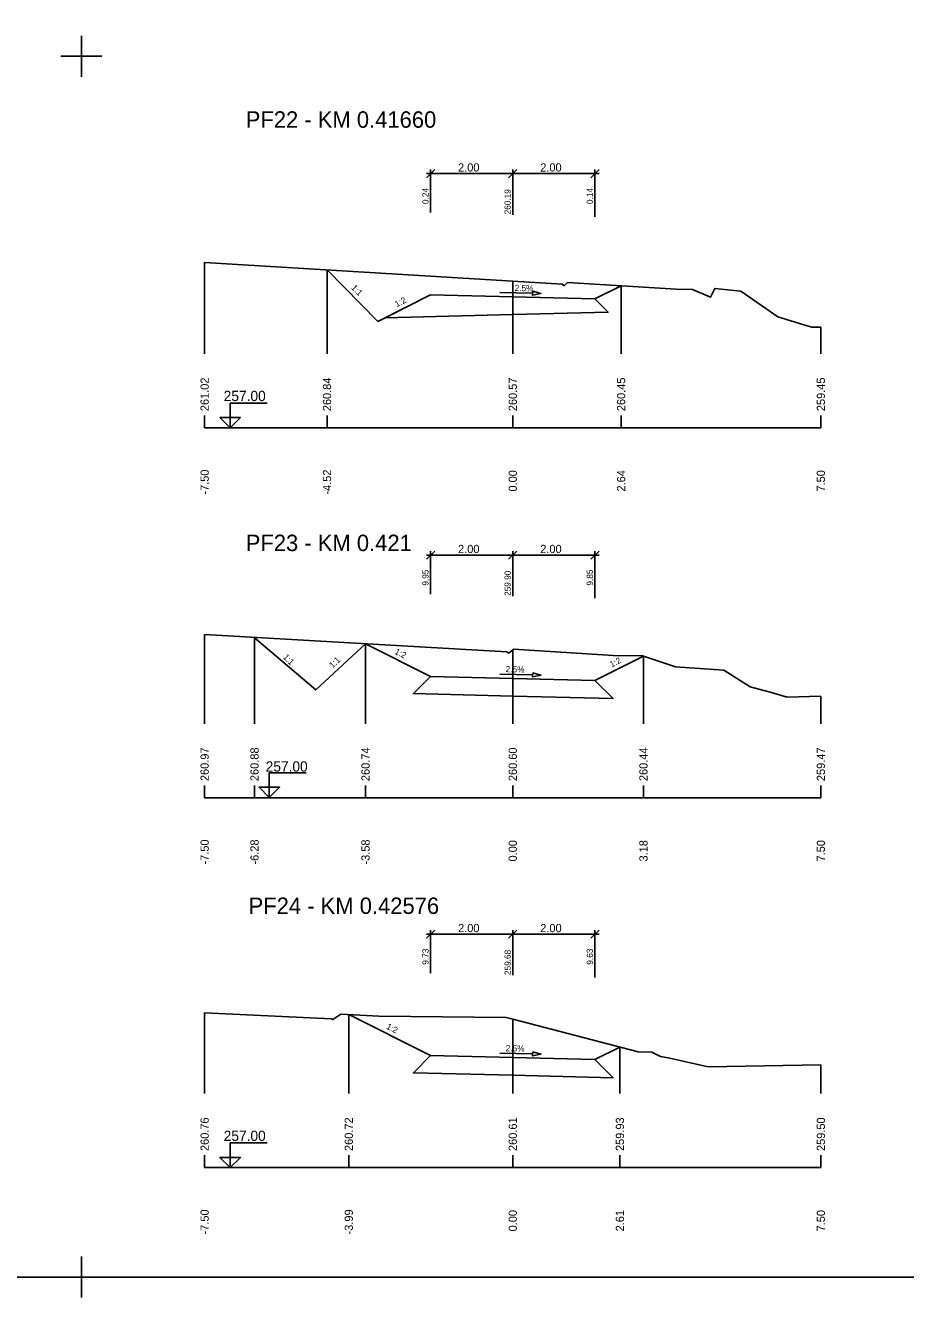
# Model space of a CAD drawing. Extents: x -5 to 1895, y -2 to 602.
# Drawn here: x 1456.4 to 1670.6, y -1.6 to 307.9 of the extents above; entities that cross this region are included whole.
import ezdxf

# ---------------------------------------------------------------- set-up
doc = ezdxf.new("R2010")
doc.units = 0
for name, color, linetype in [('KOTA', 7, 'Continuous'), ('KOTA_DELKY', 7, 'Continuous'), ('KOTA_DELKY_CONT', 7, 'Continuous'), ('NS_TELESO_VOZOVKY', 7, 'Continuous'), ('NS_V_PF', 7, 'Continuous'), ('REZY_PF_PUVODNI', 7, 'Continuous'), ('SESTAVY_REZU_PF', 7, 'Continuous'), ('SKLON', 7, 'Continuous'), ('SVK', 7, 'Continuous')]:
    doc.layers.add(name, color=color, linetype=linetype)

msp = doc.modelspace()

# ---------------------------------------------------------------- linework, layer by layer
for p, q in [((1470, 305.39), (1470, 295.39)), ((1470, 305.39), (1470, 295.39)), ((1470, 305.39), (1470, 295.39)), ((1470, 305.39), (1470, 295.39)), ((1470, 305.39), (1470, 295.39)), ((1470, 305.39), (1470, 295.39)), ((1470, 305.39), (1470, 295.39)), ((1470, 305.39), (1470, 295.39)), ((1470, 305.39), (1470, 295.39)), ((1470, 305.39), (1470, 295.39)), ((1470, 305.39), (1470, 295.39)), ((1470, 305.39), (1470, 295.39)), ((1470, 305.39), (1470, 295.39)), ((1470, 305.39), (1470, 295.39)), ((1470, 305.39), (1470, 295.39)), ((1470, 305.39), (1470, 295.39)), ((1470, 305.39), (1470, 295.39)), ((1470, 305.39), (1470, 295.39)), ((1470, 305.39), (1470, 295.39)), ((1470, 305.39), (1470, 295.39)), ((1470, 305.39), (1470, 295.39)), ((1470, 305.39), (1470, 295.39)), ((1470, 305.39), (1470, 295.39)), ((1470, 305.39), (1470, 295.39)), ((1470, 305.39), (1470, 295.39)), ((1470, 305.39), (1470, 295.39)), ((1470, 305.39), (1470, 295.39)), ((1470, 305.39), (1470, 295.39)), ((1470, 305.39), (1470, 295.39)), ((1470, 305.39), (1470, 295.39)), ((1475, 300.39), (1465, 300.39)), ((1475, 300.39), (1465, 300.39)), ((1475, 300.39), (1465, 300.39)), ((1475, 300.39), (1465, 300.39)), ((1475, 300.39), (1465, 300.39)), ((1475, 300.39), (1465, 300.39)), ((1475, 300.39), (1465, 300.39)), ((1475, 300.39), (1465, 300.39)), ((1475, 300.39), (1465, 300.39)), ((1475, 300.39), (1465, 300.39)), ((1475, 300.39), (1465, 300.39)), ((1475, 300.39), (1465, 300.39)), ((1475, 300.39), (1465, 300.39)), ((1475, 300.39), (1465, 300.39)), ((1475, 300.39), (1465, 300.39)), ((1475, 300.39), (1465, 300.39)), ((1475, 300.39), (1465, 300.39)), ((1475, 300.39), (1465, 300.39)), ((1475, 300.39), (1465, 300.39)), ((1475, 300.39), (1465, 300.39)), ((1475, 300.39), (1465, 300.39)), ((1475, 300.39), (1465, 300.39)), ((1475, 300.39), (1465, 300.39)), ((1475, 300.39), (1465, 300.39)), ((1475, 300.39), (1465, 300.39)), ((1475, 300.39), (1465, 300.39)), ((1475, 300.39), (1465, 300.39)), ((1475, 300.39), (1465, 300.39)), ((1475, 300.39), (1465, 300.39)), ((1475, 300.39), (1465, 300.39)), ((1470, 8.39), (1470, -1.61)), ((1470, 8.39), (1470, -1.61)), ((1470, 8.39), (1470, -1.61)), ((1470, 8.39), (1470, -1.61)), ((1470, 8.39), (1470, -1.61)), ((1470, 8.39), (1470, -1.61)), ((1470, 8.39), (1470, -1.61)), ((1470, 8.39), (1470, -1.61)), ((1470, 8.39), (1470, -1.61)), ((1470, 8.39), (1470, -1.61)), ((1470, 8.39), (1470, -1.61)), ((1470, 8.39), (1470, -1.61)), ((1475, 3.39), (1465, 3.39)), ((1475, 3.39), (1465, 3.39)), ((1475, 3.39), (1465, 3.39)), ((1475, 3.39), (1465, 3.39)), ((1475, 3.39), (1465, 3.39)), ((1475, 3.39), (1465, 3.39)), ((1475, 3.39), (1465, 3.39)), ((1475, 3.39), (1465, 3.39)), ((1475, 3.39), (1465, 3.39)), ((1475, 3.39), (1465, 3.39)), ((1475, 3.39), (1465, 3.39)), ((1475, 3.39), (1465, 3.39))]:
    msp.add_line(p, q)
msp.add_lwpolyline([(0, 597.39), (1890, 597.39), (1890, 3.39), (0, 3.39)], close=True)
at = {"layer": 'KOTA'}
for points in [[(1506.22, 212.5), (1503.72, 212.5), (1506.22, 210), (1506.22, 216), (1515.22, 216)], [(1506.22, 210), (1508.72, 212.5), (1506.22, 212.5)], [(1515.74, 122.55), (1513.24, 122.55), (1515.74, 120.05), (1515.74, 126.05), (1524.74, 126.05)], [(1515.74, 120.05), (1518.24, 122.55), (1515.74, 122.55)], [(1506.22, 32.5), (1503.72, 32.5), (1506.22, 30), (1506.22, 36), (1515.22, 36)], [(1506.22, 30), (1508.72, 32.5), (1506.22, 32.5)]]:
    msp.add_lwpolyline(points, dxfattribs=at)
at = {"layer": 'KOTA_DELKY'}
for points in [[(1554, 270.85), (1556, 272.85)], [(1555, 262.35), (1555, 272.85)], [(1574, 270.85), (1576, 272.85)], [(1574, 270.85), (1576, 272.85)], [(1575, 261.85), (1575, 272.85)], [(1575, 261.85), (1575, 272.85)], [(1594, 270.85), (1596, 272.85)], [(1595, 261.35), (1595, 272.85)], [(1554, 271.85), (1576, 271.85)], [(1574, 271.85), (1596, 271.85)], [(1554, 178.02), (1556, 180.02)], [(1555, 169.52), (1555, 180.02)], [(1574, 178.02), (1576, 180.02)], [(1574, 178.02), (1576, 180.02)], [(1575, 169.02), (1575, 180.02)], [(1575, 169.02), (1575, 180.02)], [(1594, 178.02), (1596, 180.02)], [(1595, 168.52), (1595, 180.02)], [(1554, 179.02), (1576, 179.02)], [(1574, 179.02), (1596, 179.02)], [(1554, 85.79), (1556, 87.79)], [(1554, 86.79), (1576, 86.79)], [(1555, 77.29), (1555, 87.79)], [(1574, 85.79), (1576, 87.79)], [(1574, 85.79), (1576, 87.79)], [(1574, 86.79), (1596, 86.79)], [(1575, 76.79), (1575, 87.79)], [(1575, 76.79), (1575, 87.79)], [(1594, 85.79), (1596, 87.79)], [(1595, 76.29), (1595, 87.79)]]:
    msp.add_lwpolyline(points, dxfattribs=at)
at = {"layer": 'NS_TELESO_VOZOVKY'}
for points in [[(1575, 241.85), (1595, 241.35), (1595, 241.35), (1598.22, 238.13), (1575, 237.55), (1543.97, 236.78), (1555, 242.35), (1555, 242.35), (1575, 241.85)], [(1575, 149.02), (1595, 148.52), (1595, 148.52), (1599.41, 144.11), (1575, 144.72), (1550.8, 145.32), (1555, 149.52), (1555, 149.52), (1575, 149.02)], [(1575, 56.79), (1595, 56.29), (1595, 56.29), (1599.41, 51.88), (1575, 52.49), (1550.8, 53.09), (1555, 57.29), (1555, 57.29), (1575, 56.79)]]:
    msp.add_lwpolyline(points, dxfattribs=at)
at = {"layer": 'NS_V_PF'}
for points in [[(1529.79, 248.41), (1542.19, 235.88), (1555, 242.35), (1555, 242.35), (1575, 241.85), (1595, 241.35), (1595, 241.35), (1601.38, 244.54)], [(1512.04, 158.99), (1527.04, 146.23), (1539.16, 157.44)], [(1539.16, 157.44), (1555, 149.52), (1555, 149.52), (1575, 149.02), (1595, 148.52), (1595, 148.52), (1606.81, 154.42)], [(1535.09, 67.24), (1555, 57.29), (1555, 57.29), (1575, 56.79), (1595, 56.29), (1595, 56.29), (1601.08, 59.33)]]:
    msp.add_lwpolyline(points, dxfattribs=at)
at = {"layer": 'REZY_PF_PUVODNI'}
for points in [[(1500, 250.19), (1575, 245.7), (1587.01, 244.98), (1587.54, 244.54), (1588.36, 245.37), (1614.74, 243.69), (1618.72, 243.63), (1623.15, 241.79), (1624.15, 243.92), (1630.5, 243.26), (1639.56, 236.96), (1645.84, 235.09), (1647.82, 234.45), (1650, 234.51)], [(1500, 159.68), (1573.59, 155.46), (1574.03, 155.13), (1575, 156), (1575.18, 156.16), (1600.74, 154.54), (1606.32, 154.59), (1614.63, 151.83), (1626.38, 151.03), (1632.81, 147.01), (1637.66, 145.71), (1641.81, 144.49), (1650, 144.68)], [(1500, 67.64), (1530.87, 66.19), (1531.17, 66.02), (1533.15, 67.35), (1542.44, 66.84), (1573.38, 66.56), (1575, 66.14), (1605.53, 58.17), (1608.82, 58.09), (1610.97, 57.07), (1612.8, 56.7), (1622.53, 54.55), (1650, 55.01)]]:
    msp.add_lwpolyline(points, dxfattribs=at)
at = {"layer": 'SESTAVY_REZU_PF'}
for points in [[(1500, 210), (1650, 210)], [(1500, 120), (1650, 120)], [(1500, 30), (1650, 30)]]:
    msp.add_lwpolyline(points, dxfattribs=at)
at = {"layer": 'SKLON'}
for points in [[(1571.85, 242.93), (1579.85, 242.73)], [(1579.86, 243.23), (1581.85, 242.68), (1579.83, 242.23), (1579.86, 243.23)], [(1571.85, 150.1), (1579.85, 149.9)], [(1579.86, 150.4), (1581.85, 149.85), (1579.83, 149.4), (1579.86, 150.4)], [(1571.85, 57.87), (1579.85, 57.67)], [(1579.86, 58.17), (1581.85, 57.62), (1579.83, 57.17), (1579.86, 58.17)]]:
    msp.add_lwpolyline(points, dxfattribs=at)
at = {"layer": 'SVK'}
for points in [[(1500, 228), (1500, 250.19)], [(1529.79, 228), (1529.79, 248.41)], [(1575, 228), (1575, 245.7)], [(1601.38, 228), (1601.38, 244.54)], [(1650, 228), (1650, 234.51)], [(1500, 210), (1500, 213)], [(1529.79, 210), (1529.79, 213)], [(1575, 210), (1575, 213)], [(1601.38, 210), (1601.38, 213)], [(1650, 210), (1650, 213)], [(1500, 138), (1500, 159.68)], [(1512.14, 138), (1512.14, 158.69)], [(1539.16, 138), (1539.16, 157.44)], [(1575, 138), (1575, 156)], [(1606.81, 138), (1606.81, 154.42)], [(1650, 138), (1650, 144.68)], [(1500, 120), (1500, 123)], [(1512.14, 120), (1512.14, 123)], [(1539.16, 120), (1539.16, 123)], [(1575, 120), (1575, 123)], [(1606.81, 120), (1606.81, 123)], [(1650, 120), (1650, 123)], [(1500, 48), (1500, 67.64)], [(1535.09, 48), (1535.09, 67.24)], [(1575, 48), (1575, 66.14)], [(1601.08, 48), (1601.08, 59.33)], [(1650, 48), (1650, 55.01)], [(1500, 30), (1500, 33)], [(1535.09, 30), (1535.09, 33)], [(1575, 30), (1575, 33)], [(1601.08, 30), (1601.08, 33)], [(1650, 30), (1650, 33)]]:
    msp.add_lwpolyline(points, dxfattribs=at)

# ---------------------------------------------------------------- texts
at = {"layer": 'KOTA'}
for p in [(1504.64, 216.5), (1514.86, 126.35), (1504.64, 36.5)]:
    msp.add_text('257.00', height=2.5, dxfattribs=at).set_placement(p)
at = {"layer": 'KOTA_DELKY'}
for p in [(1561.69, 272.35), (1581.69, 272.35), (1561.69, 179.52), (1581.69, 179.52), (1561.69, 87.29), (1581.69, 87.29)]:
    msp.add_text('2.00', height=2, dxfattribs=at).set_placement(p)
at = {"layer": 'KOTA_DELKY_CONT'}
for s, p in [('0.24', (1554.5, 264.44)), ('260.19', (1574.5, 261.93)), ('0.14', (1594.5, 264.44)), ('9.95', (1554.5, 171.61)), ('259.90', (1574.5, 169.1)), ('9.85', (1594.5, 171.61)), ('9.73', (1554.5, 79.38)), ('259.68', (1574.5, 76.86)), ('9.63', (1594.5, 79.38))]:
    msp.add_text(s, height=1.5, rotation=90, dxfattribs=at).set_placement(p)
at = {"layer": 'SESTAVY_REZU_PF'}
for s, p in [('PF22 - KM 0.41660', (1510, 283)), ('PF23 - KM 0.421', (1510, 180)), ('PF24 - KM 0.42576', (1510.7, 91.72))]:
    msp.add_text(s, height=4, dxfattribs=at).set_placement(p)
at = {"layer": 'SKLON'}
for s, rotation, p in [('1:1', 314.7121, (1535.59, 243.97)), ('2.5%', 358.5679, (1575.45, 243.3)), ('1:2', 26.8233, (1546.74, 239.3)), ('1:1', 314.7121, (1518.96, 154.1)), ('1:2', 333.4349, (1546.12, 155.08)), ('1:1', 44.7121, (1531.17, 151.41)), ('2.5%', 358.5679, (1573.27, 150.56)), ('1:2', 26.5651, (1599.05, 151.66)), ('1:2', 333.4349, (1544.08, 63.86)), ('2.5%', 358.5679, (1573.27, 58.33))]:
    msp.add_text(s, height=1.5, rotation=rotation, dxfattribs=at).set_placement(p)
at = {"layer": 'SVK'}
for s, p in [(' 261.02', (1501, 213.3)), (' 260.84', (1530.79, 213.3)), (' 260.57', (1576, 213.3)), (' 260.45', (1602.38, 213.3)), (' 259.45', (1651, 213.3)), (' -7.50', (1501, 193)), (' -4.52', (1530.79, 193)), ('  0.00', (1576, 193)), ('  2.64', (1602.38, 193)), ('  7.50', (1651, 193)), (' 260.97', (1501, 123.3)), (' 260.88', (1513.14, 123.3)), (' 260.74', (1540.16, 123.3)), (' 260.60', (1576, 123.3)), (' 260.44', (1607.81, 123.3)), (' 259.47', (1651, 123.3)), (' -7.50', (1501, 103)), (' -6.28', (1513.14, 103)), (' -3.58', (1540.16, 103)), ('  0.00', (1576, 103)), ('  3.18', (1607.81, 103)), ('  7.50', (1651, 103)), (' 260.76', (1501, 33.3)), (' 260.72', (1536.09, 33.3)), (' 260.61', (1576, 33.3)), (' 259.93', (1602.08, 33.3)), (' 259.50', (1651, 33.3)), (' -7.50', (1501, 13)), (' -3.99', (1536.09, 13)), ('  0.00', (1576, 13)), ('  2.61', (1602.08, 13)), ('  7.50', (1651, 13))]:
    msp.add_text(s, height=2, rotation=90, dxfattribs=at).set_placement(p)

doc.saveas('drawing.dxf')
